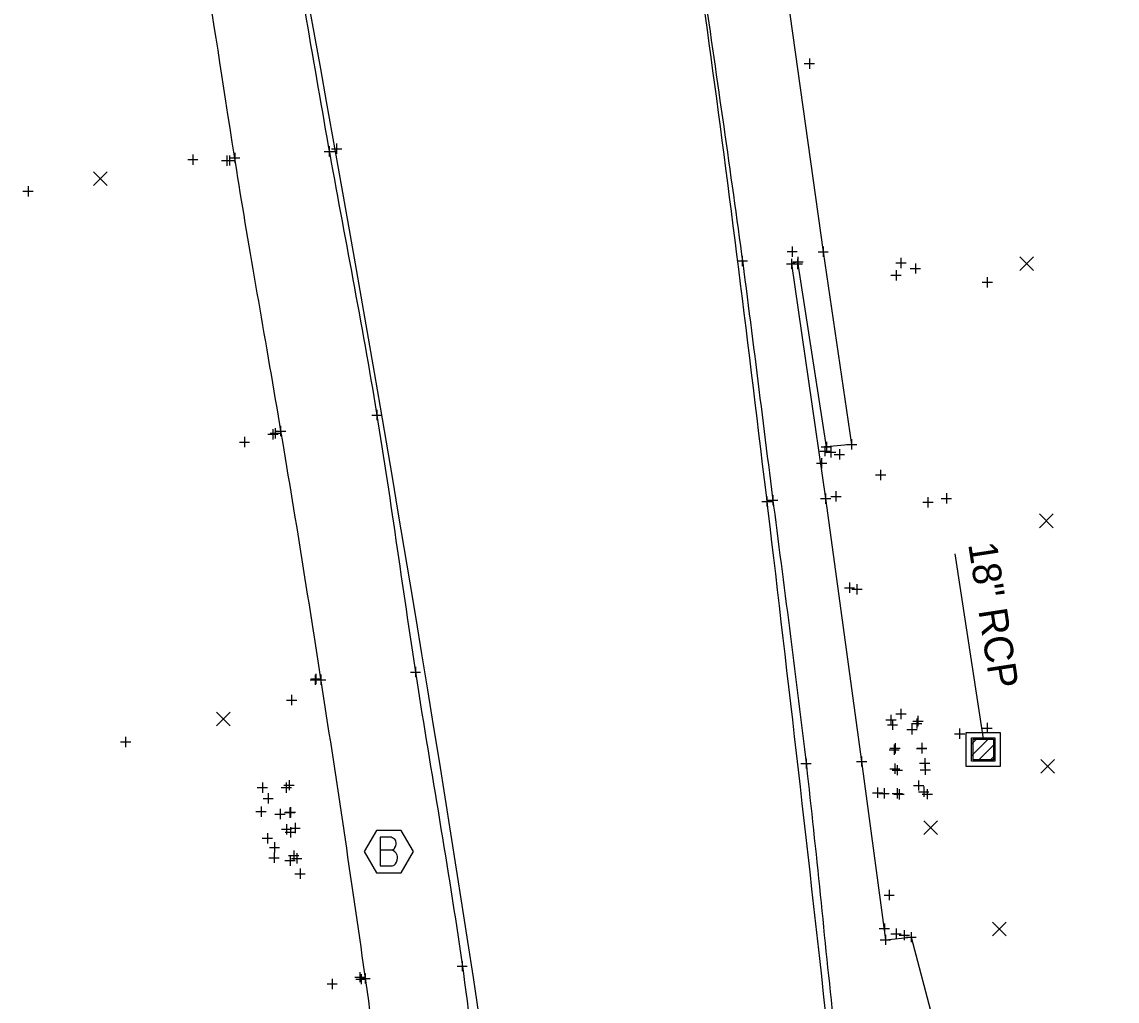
# Model space of a CAD drawing. Extents: x 2188719 to 2189819, y 654569 to 659504.
# Drawn here: x 2189678.2 to 2189785.2, y 658157.5 to 658253.3 of the extents above; entities that cross this region are included whole.
import ezdxf

# ---------------------------------------------------------------- set-up
doc = ezdxf.new("R2010")
doc.units = 0
for name, color, linetype in [('DR_X_Cells', 7, 'Continuous'), ('DR_X_Storm_Sewer', 7, 'Continuous'), ('DR_X_Text', 7, 'Continuous'), ('GK_Drainage_Nodes', 7, 'Continuous'), ('PM_X_Edge_Line', 7, 'Continuous'), ('PM_X_Transverse_Line', 7, 'Continuous'), ('PV_X_EOP', 7, 'Continuous'), ('PV_X_Shoulder', 7, 'Continuous'), ('RD_X_Cells', 7, 'Continuous'), ('SV_X_Random_Point', 7, 'Continuous'), ('SV_X_Shot_Marker', 7, 'Continuous')]:
    doc.layers.add(name, color=color, linetype=linetype)

msp = doc.modelspace()

# ---------------------------------------------------------------- linework, layer by layer
at = {"layer": 'DR_X_Cells'}
for p, q in [((2189770.99, 658181.51), (2189772.75, 658183.27)), ((2189770.99, 658182.65), (2189771.62, 658183.27)), ((2189771.59, 658180.98), (2189773.28, 658182.68)), ((2189772.72, 658180.98), (2189773.28, 658181.54))]:
    msp.add_line(p, q, dxfattribs=at)
for points in [[(2189770.47, 658183.79), (2189773.8, 658183.79), (2189773.8, 658180.46), (2189770.47, 658180.46)], [(2189770.99, 658183.27), (2189773.28, 658183.27), (2189773.28, 658180.98), (2189770.99, 658180.98)], [(2189771.14, 658183.13), (2189773.14, 658183.13), (2189773.14, 658181.13), (2189771.14, 658181.13)]]:
    msp.add_lwpolyline(points, close=True, dxfattribs=at)
at = {"layer": 'DR_X_Storm_Sewer'}
msp.add_line((2189772.17, 658183.17), (2189769.39, 658201.25), dxfattribs=at)
at = {"layer": 'GK_Drainage_Nodes'}
for p, q in [((2189772.14, 658183.79), (2189772.14, 658183.79)), ((2189772.14, 658183.13), (2189772.14, 658183.13)), ((2189771.14, 658182.13), (2189771.14, 658182.13)), ((2189772.14, 658182.13), (2189772.14, 658182.13)), ((2189772.14, 658182.13), (2189772.14, 658182.13)), ((2189772.14, 658182.13), (2189772.14, 658182.13)), ((2189773.14, 658182.13), (2189773.14, 658182.13)), ((2189772.14, 658181.13), (2189772.14, 658181.13)), ((2189772.14, 658180.46), (2189772.14, 658180.46))]:
    msp.add_line(p, q, dxfattribs=at)
at = {"layer": 'PM_X_Edge_Line'}
msp.add_open_spline([(2189715.92, 658416.15), (2189719.55, 658398.42), (2189727.31, 658355.37), (2189741.15, 658285.79), (2189752.08, 658199.49), (2189764.73, 658083.92), (2189776.67, 657949.48), (2189785.57, 657773.05), (2189784.87, 657651.45), (2189781.91, 657575.63)], degree=3, dxfattribs=at)
at = {"layer": 'PM_X_Transverse_Line'}
msp.add_open_spline([(2189687.91, 658347.82), (2189695.6, 658312.27), (2189724.53, 658165.17), (2189751.08, 657933.72), (2189754.2, 657738.17), (2189752.07, 657655.83)], degree=3, dxfattribs=at)
at = {"layer": 'PV_X_EOP'}
for points in [[(2189715.65, 658416.09), (2189717.36, 658407.13), (2189721.67, 658389.5), (2189726.25, 658363.76), (2189732.27, 658338.61), (2189735.95, 658313.21), (2189740.83, 658286.81), (2189744.4, 658258.95), (2189748.43, 658232.12), (2189751.61, 658205.72), (2189755.02, 658180.62), (2189757.39, 658155.27), (2189760.52, 658129.99), (2189762.73, 658103.87), (2189765.52, 658076.79), (2189767.84, 658049.53), (2189770.28, 658023.15), (2189773.03, 657997.24), (2189774.6, 657969.67), (2189777.01, 657941.26), (2189778.8, 657911.99), (2189780.69, 657884.09), (2189781.4, 657856.58), (2189782.11, 657829.65), (2189783.53, 657801.33), (2189783.56, 657772.66), (2189783.96, 657743.23), (2189783.95, 657715.3), (2189783.44, 657687.6), (2189783.88, 657660.21), (2189783.01, 657632.25), (2189782.93, 657604.05), (2189782.64, 657585.12), (2189782.5, 657575.65)], [(2189686.87, 658347.88), (2189688.95, 658339.56), (2189693.17, 658321.78), (2189697.87, 658294.9), (2189703.7, 658267.62), (2189707.98, 658241.03), (2189713.11, 658215.13), (2189716.61, 658188.45), (2189721.68, 658160.42), (2189724.61, 658131.33), (2189729.42, 658103.12), (2189732.17, 658074.94), (2189735.91, 658046.42), (2189738.42, 658016.97), (2189741.68, 657987.88), (2189743.15, 657958.86), (2189745.92, 657930.4), (2189747.37, 657902.49), (2189749.54, 657874.27), (2189750.21, 657845.72), (2189752.04, 657816.78), (2189752.93, 657788.08), (2189753.38, 657759.61), (2189754.01, 657732.65), (2189754.13, 657706.9), (2189754.02, 657681.8), (2189752.87, 657664.76), (2189752.08, 657656.03)]]:
    msp.add_open_spline(points, degree=3, dxfattribs=at)
at = {"layer": 'PV_X_Shoulder'}
for p, q in [((2189752.4, 658260.05), (2189756.49, 658230.8)), ((2189754.03, 658229.81), (2189753.4, 658229.61)), ((2189756.81, 658211.72), (2189754.03, 658229.81)), ((2189756.49, 658230.8), (2189759.27, 658211.96)), ((2189753.4, 658229.61), (2189756.73, 658206.66)), ((2189759.27, 658211.96), (2189756.81, 658211.72)), ((2189756.73, 658206.66), (2189760.25, 658180.96)), ((2189760.25, 658180.96), (2189762.57, 658163.53)), ((2189762.57, 658163.53), (2189765.08, 658163.79)), ((2189765.08, 658163.79), (2189767.29, 658155.51))]:
    msp.add_line(p, q, dxfattribs=at)
msp.add_open_spline([(2189678.17, 658346.51), (2189680.12, 658338.02), (2189683.83, 658320.14), (2189688.68, 658299.1), (2189690.22, 658284.76), (2189692.33, 658279.09), (2189693.11, 658275.51), (2189692.87, 658271.06), (2189696.13, 658259.46), (2189698.82, 658239.7), (2189703.41, 658214.08), (2189707.68, 658187.35), (2189711.85, 658159.43), (2189715.66, 658130.84), (2189719.89, 658102.92), (2189722.84, 658074.64), (2189726.21, 658045.96), (2189729.3, 658016.08), (2189731.79, 657986.57), (2189734.56, 657957.49), (2189736.24, 657929.57), (2189738.31, 657902.49), (2189739.34, 657874.4), (2189741.63, 657845.81), (2189742.72, 657816.8), (2189743.78, 657788), (2189744.99, 657759.47), (2189745.29, 657733.99), (2189744.96, 657716.97), (2189745.15, 657707.52), (2189744.91, 657697.88), (2189745.01, 657680.84), (2189744.6, 657665.71), (2189744.35, 657657.17)], degree=3, dxfattribs=at)
at = {"layer": 'RD_X_Cells'}
for p, q in [((2189712.84, 658174.23), (2189711.64, 658172.16)), ((2189715.24, 658174.23), (2189712.84, 658174.23)), ((2189716.44, 658172.16), (2189715.24, 658174.23)), ((2189711.64, 658172.16), (2189712.84, 658170.08)), ((2189715.24, 658170.08), (2189716.44, 658172.16)), ((2189712.84, 658170.08), (2189715.24, 658170.08))]:
    msp.add_line(p, q, dxfattribs=at)
msp.add_lwpolyline([(2189714.4, 658172.28), (2189714.51, 658172.39), (2189714.58, 658172.45), (2189714.62, 658172.52), (2189714.64, 658172.56), (2189714.69, 658172.65), (2189714.71, 658172.72), (2189714.75, 658172.87), (2189714.75, 658172.94), (2189714.75, 658173.03), (2189714.73, 658173.16), (2189714.69, 658173.27), (2189714.62, 658173.36), (2189714.51, 658173.45), (2189714.42, 658173.49), (2189714.38, 658173.51), (2189714.27, 658173.56), (2189713.19, 658173.56), (2189713.19, 658170.76), (2189714.4, 658170.76), (2189714.56, 658170.84), (2189714.69, 658170.95), (2189714.8, 658171.13), (2189714.86, 658171.33), (2189714.89, 658171.53), (2189714.89, 658171.66), (2189714.84, 658171.79), (2189714.75, 658171.99), (2189714.64, 658172.12), (2189714.4, 658172.28), (2189713.19, 658172.28)], dxfattribs=at)
at = {"layer": 'SV_X_Random_Point'}
for p, q in [((2189685.18, 658237.26), (2189686.51, 658238.59)), ((2189685.18, 658238.59), (2189686.51, 658237.26)), ((2189775.72, 658228.96), (2189777.05, 658230.3)), ((2189775.72, 658230.3), (2189777.05, 658228.96)), ((2189777.62, 658203.82), (2189778.96, 658205.16)), ((2189777.62, 658205.16), (2189778.96, 658203.82)), ((2189697.19, 658184.46), (2189698.53, 658185.79)), ((2189697.19, 658185.79), (2189698.53, 658184.46)), ((2189777.76, 658179.82), (2189779.09, 658181.16)), ((2189777.76, 658181.16), (2189779.09, 658179.82)), ((2189766.33, 658173.83), (2189767.66, 658175.17)), ((2189766.33, 658175.17), (2189767.66, 658173.83)), ((2189773.04, 658163.91), (2189774.38, 658165.24)), ((2189773.04, 658165.24), (2189774.38, 658163.91))]:
    msp.add_line(p, q, dxfattribs=at)
at = {"layer": 'SV_X_Shot_Marker'}
for p, q in [((2189754.65, 658249.19), (2189755.65, 658249.19)), ((2189755.15, 658249.69), (2189755.15, 658248.69)), ((2189755.15, 658249.19), (2189755.15, 658249.19)), ((2189707.72, 658240.6), (2189708.72, 658240.6)), ((2189708.22, 658241.1), (2189708.22, 658240.1)), ((2189708.22, 658240.6), (2189708.22, 658240.6)), ((2189708.43, 658240.86), (2189709.43, 658240.86)), ((2189708.93, 658241.36), (2189708.93, 658240.36)), ((2189708.93, 658240.86), (2189708.93, 658240.86)), ((2189694.38, 658239.8), (2189695.38, 658239.8)), ((2189694.88, 658240.3), (2189694.88, 658239.3)), ((2189694.88, 658239.8), (2189694.88, 658239.8)), ((2189697.69, 658239.7), (2189698.69, 658239.7)), ((2189697.95, 658239.71), (2189698.95, 658239.71)), ((2189698.19, 658240.2), (2189698.19, 658239.2)), ((2189698.19, 658239.7), (2189698.19, 658239.7)), ((2189698.45, 658240.21), (2189698.45, 658239.21)), ((2189698.45, 658239.71), (2189698.45, 658239.71)), ((2189698.47, 658239.96), (2189699.47, 658239.96)), ((2189698.97, 658240.46), (2189698.97, 658239.46)), ((2189698.97, 658239.96), (2189698.97, 658239.96)), ((2189678.28, 658236.7), (2189679.28, 658236.7)), ((2189678.78, 658237.2), (2189678.78, 658236.2)), ((2189678.78, 658236.7), (2189678.78, 658236.7)), ((2189753.46, 658231.31), (2189753.46, 658230.31)), ((2189756.49, 658231.3), (2189756.49, 658230.3)), ((2189748.09, 658229.9), (2189749.09, 658229.9)), ((2189748.59, 658230.4), (2189748.59, 658229.4)), ((2189748.59, 658229.9), (2189748.59, 658229.9)), ((2189752.96, 658230.81), (2189753.96, 658230.81)), ((2189753.4, 658230.11), (2189753.4, 658229.11)), ((2189753.46, 658230.81), (2189753.46, 658230.81)), ((2189753.53, 658229.81), (2189754.53, 658229.81)), ((2189753.97, 658230.1), (2189753.97, 658229.1)), ((2189754.03, 658230.31), (2189754.03, 658229.31)), ((2189754.03, 658229.81), (2189754.03, 658229.81)), ((2189755.99, 658230.8), (2189756.99, 658230.8)), ((2189756.49, 658230.8), (2189756.49, 658230.8)), ((2189764.09, 658230.2), (2189764.09, 658229.2)), ((2189752.9, 658229.61), (2189753.9, 658229.61)), ((2189753.4, 658229.61), (2189753.4, 658229.61)), ((2189753.47, 658229.6), (2189754.47, 658229.6)), ((2189753.97, 658229.6), (2189753.97, 658229.6)), ((2189763.59, 658229.7), (2189764.59, 658229.7)), ((2189763.61, 658228.99), (2189763.61, 658227.99)), ((2189764.09, 658229.7), (2189764.09, 658229.7)), ((2189765, 658229.16), (2189766, 658229.16)), ((2189765.5, 658229.66), (2189765.5, 658228.66)), ((2189765.5, 658229.16), (2189765.5, 658229.16)), ((2189763.11, 658228.49), (2189764.11, 658228.49)), ((2189763.61, 658228.49), (2189763.61, 658228.49)), ((2189772.03, 658227.81), (2189773.03, 658227.81)), ((2189772.53, 658228.31), (2189772.53, 658227.31)), ((2189772.53, 658227.81), (2189772.53, 658227.81)), ((2189712.37, 658214.83), (2189713.37, 658214.83)), ((2189712.87, 658215.33), (2189712.87, 658214.33)), ((2189712.87, 658214.83), (2189712.87, 658214.83)), ((2189703.46, 658213.76), (2189703.46, 658212.76)), ((2189699.93, 658212.69), (2189699.93, 658211.69)), ((2189702.21, 658212.95), (2189703.21, 658212.95)), ((2189702.44, 658213.05), (2189703.44, 658213.05)), ((2189702.71, 658213.45), (2189702.71, 658212.45)), ((2189702.71, 658212.95), (2189702.71, 658212.95)), ((2189702.94, 658213.55), (2189702.94, 658212.55)), ((2189702.94, 658213.05), (2189702.94, 658213.05)), ((2189702.96, 658213.26), (2189703.96, 658213.26)), ((2189703.46, 658213.26), (2189703.46, 658213.26)), ((2189699.43, 658212.19), (2189700.43, 658212.19)), ((2189699.93, 658212.19), (2189699.93, 658212.19)), ((2189756.31, 658211.72), (2189757.31, 658211.72)), ((2189756.67, 658211.8), (2189756.67, 658210.8)), ((2189756.81, 658212.22), (2189756.81, 658211.22)), ((2189756.81, 658211.72), (2189756.81, 658211.72)), ((2189757.23, 658211.69), (2189757.23, 658210.69)), ((2189758.77, 658211.96), (2189759.77, 658211.96)), ((2189759.27, 658212.46), (2189759.27, 658211.46)), ((2189759.27, 658211.96), (2189759.27, 658211.96)), ((2189756.17, 658211.3), (2189757.17, 658211.3)), ((2189756.34, 658210.61), (2189756.34, 658209.61)), ((2189756.67, 658211.3), (2189756.67, 658211.3)), ((2189756.73, 658211.19), (2189757.73, 658211.19)), ((2189757.23, 658211.19), (2189757.23, 658211.19)), ((2189757.58, 658210.98), (2189758.58, 658210.98)), ((2189758.08, 658211.48), (2189758.08, 658210.48)), ((2189758.08, 658210.98), (2189758.08, 658210.98)), ((2189755.84, 658210.11), (2189756.84, 658210.11)), ((2189756.34, 658210.11), (2189756.34, 658210.11)), ((2189762.11, 658209.48), (2189762.11, 658208.48)), ((2189761.61, 658208.98), (2189762.61, 658208.98)), ((2189762.11, 658208.98), (2189762.11, 658208.98)), ((2189757.74, 658207.38), (2189757.74, 658206.38)), ((2189750.5, 658206.38), (2189751.5, 658206.38)), ((2189751, 658206.88), (2189751, 658205.88)), ((2189751, 658206.38), (2189751, 658206.38)), ((2189751.07, 658206.51), (2189752.07, 658206.51)), ((2189751.57, 658207.01), (2189751.57, 658206.01)), ((2189751.57, 658206.51), (2189751.57, 658206.51)), ((2189756.23, 658206.66), (2189757.23, 658206.66)), ((2189756.73, 658207.16), (2189756.73, 658206.16)), ((2189756.73, 658206.66), (2189756.73, 658206.66)), ((2189757.24, 658206.88), (2189758.24, 658206.88)), ((2189757.74, 658206.88), (2189757.74, 658206.88)), ((2189766.23, 658206.3), (2189767.23, 658206.3)), ((2189766.73, 658206.8), (2189766.73, 658205.8)), ((2189766.73, 658206.3), (2189766.73, 658206.3)), ((2189768.04, 658206.68), (2189769.04, 658206.68)), ((2189768.54, 658207.18), (2189768.54, 658206.18)), ((2189768.54, 658206.68), (2189768.54, 658206.68)), ((2189758.56, 658197.95), (2189759.56, 658197.95)), ((2189759.06, 658198.45), (2189759.06, 658197.45)), ((2189759.06, 658197.95), (2189759.06, 658197.95)), ((2189759.29, 658197.8), (2189760.29, 658197.8)), ((2189759.79, 658198.3), (2189759.79, 658197.3)), ((2189759.79, 658197.8), (2189759.79, 658197.8)), ((2189716.64, 658190.2), (2189716.64, 658189.2)), ((2189706.85, 658189.45), (2189706.85, 658188.45)), ((2189706.9, 658189.53), (2189706.9, 658188.53)), ((2189707.38, 658189.46), (2189707.38, 658188.46)), ((2189716.14, 658189.7), (2189717.14, 658189.7)), ((2189716.64, 658189.7), (2189716.64, 658189.7)), ((2189706.35, 658188.95), (2189707.35, 658188.95)), ((2189706.4, 658189.03), (2189707.4, 658189.03)), ((2189706.85, 658188.95), (2189706.85, 658188.95)), ((2189706.88, 658188.96), (2189707.88, 658188.96)), ((2189706.9, 658189.03), (2189706.9, 658189.03)), ((2189707.38, 658188.96), (2189707.38, 658188.96)), ((2189704.54, 658187.47), (2189704.54, 658186.47)), ((2189704.04, 658186.97), (2189705.04, 658186.97)), ((2189704.54, 658186.97), (2189704.54, 658186.97)), ((2189764.09, 658186.11), (2189764.09, 658185.11)), ((2189762.61, 658185.03), (2189763.61, 658185.03)), ((2189763.11, 658185.53), (2189763.11, 658184.53)), ((2189763.11, 658185.03), (2189763.11, 658185.03)), ((2189763.27, 658185.06), (2189763.27, 658184.06)), ((2189763.59, 658185.61), (2189764.59, 658185.61)), ((2189764.09, 658185.61), (2189764.09, 658185.61)), ((2189765.25, 658184.91), (2189766.25, 658184.91)), ((2189765.63, 658185.18), (2189765.63, 658184.18)), ((2189765.75, 658185.41), (2189765.75, 658184.41)), ((2189765.75, 658184.91), (2189765.75, 658184.91)), ((2189762.77, 658184.56), (2189763.77, 658184.56)), ((2189763.27, 658184.56), (2189763.27, 658184.56)), ((2189764.67, 658184.09), (2189765.67, 658184.09)), ((2189765.13, 658184.68), (2189766.13, 658184.68)), ((2189765.17, 658184.59), (2189765.17, 658183.59)), ((2189765.17, 658184.09), (2189765.17, 658184.09)), ((2189765.63, 658184.68), (2189765.63, 658184.68)), ((2189769.83, 658184.18), (2189769.83, 658183.18)), ((2189772.02, 658184.23), (2189773.02, 658184.23)), ((2189772.52, 658184.73), (2189772.52, 658183.73)), ((2189772.52, 658184.23), (2189772.52, 658184.23)), ((2189687.81, 658182.87), (2189688.81, 658182.87)), ((2189688.31, 658183.37), (2189688.31, 658182.37)), ((2189688.31, 658182.87), (2189688.31, 658182.87)), ((2189763.52, 658182.75), (2189763.52, 658181.75)), ((2189766.12, 658182.74), (2189766.12, 658181.74)), ((2189766.13, 658182.77), (2189766.13, 658181.77)), ((2189769.33, 658183.68), (2189770.33, 658183.68)), ((2189769.83, 658183.68), (2189769.83, 658183.68)), ((2189762.93, 658182.11), (2189763.93, 658182.11)), ((2189763.02, 658182.25), (2189764.02, 658182.25)), ((2189763.43, 658182.61), (2189763.43, 658181.61)), ((2189763.43, 658182.11), (2189763.43, 658182.11)), ((2189763.52, 658182.25), (2189763.52, 658182.25)), ((2189765.62, 658182.24), (2189766.62, 658182.24)), ((2189765.63, 658182.27), (2189766.63, 658182.27)), ((2189766.12, 658182.24), (2189766.12, 658182.24)), ((2189766.13, 658182.27), (2189766.13, 658182.27)), ((2189754.32, 658180.77), (2189755.32, 658180.77)), ((2189754.82, 658181.27), (2189754.82, 658180.27)), ((2189754.82, 658180.77), (2189754.82, 658180.77)), ((2189759.75, 658180.96), (2189760.75, 658180.96)), ((2189760.25, 658181.46), (2189760.25, 658180.46)), ((2189760.25, 658180.96), (2189760.25, 658180.96)), ((2189763.5, 658180.76), (2189763.5, 658179.76)), ((2189763.74, 658180.61), (2189763.74, 658179.61)), ((2189765.92, 658180.8), (2189766.92, 658180.8)), ((2189766.42, 658181.3), (2189766.42, 658180.3)), ((2189766.42, 658180.8), (2189766.42, 658180.8)), ((2189766.47, 658180.66), (2189766.47, 658179.66)), ((2189763, 658180.26), (2189764, 658180.26)), ((2189763.24, 658180.11), (2189764.24, 658180.11)), ((2189763.5, 658180.26), (2189763.5, 658180.26)), ((2189763.74, 658180.11), (2189763.74, 658180.11)), ((2189765.97, 658180.16), (2189766.97, 658180.16)), ((2189766.47, 658180.16), (2189766.47, 658180.16)), ((2189701.68, 658178.91), (2189701.68, 658177.91)), ((2189703.79, 658178.65), (2189704.79, 658178.65)), ((2189704.01, 658178.91), (2189704.01, 658177.91)), ((2189704.29, 658179.15), (2189704.29, 658178.15)), ((2189704.29, 658178.65), (2189704.29, 658178.65)), ((2189765.32, 658178.62), (2189766.32, 658178.62)), ((2189765.82, 658179.12), (2189765.82, 658178.12)), ((2189765.82, 658178.62), (2189765.82, 658178.62)), ((2189766.32, 658178.51), (2189766.32, 658177.51)), ((2189701.18, 658178.41), (2189702.18, 658178.41)), ((2189701.68, 658178.41), (2189701.68, 658178.41)), ((2189702.24, 658177.85), (2189702.24, 658176.85)), ((2189703.51, 658178.41), (2189704.51, 658178.41)), ((2189704.01, 658178.41), (2189704.01, 658178.41)), ((2189761.31, 658177.91), (2189762.31, 658177.91)), ((2189761.81, 658178.41), (2189761.81, 658177.41)), ((2189761.81, 658177.91), (2189761.81, 658177.91)), ((2189761.95, 658177.84), (2189762.95, 658177.84)), ((2189762.45, 658178.34), (2189762.45, 658177.34)), ((2189762.45, 658177.84), (2189762.45, 658177.84)), ((2189763.24, 658177.84), (2189764.24, 658177.84)), ((2189763.41, 658177.76), (2189764.41, 658177.76)), ((2189763.74, 658178.34), (2189763.74, 658177.34)), ((2189763.74, 658177.84), (2189763.74, 658177.84)), ((2189763.91, 658178.26), (2189763.91, 658177.26)), ((2189763.91, 658177.76), (2189763.91, 658177.76)), ((2189765.82, 658178.01), (2189766.82, 658178.01)), ((2189766.17, 658177.77), (2189767.17, 658177.77)), ((2189766.32, 658178.01), (2189766.32, 658178.01)), ((2189766.67, 658178.27), (2189766.67, 658177.27)), ((2189766.67, 658177.77), (2189766.67, 658177.77)), ((2189701.55, 658176.56), (2189701.55, 658175.56)), ((2189701.74, 658177.35), (2189702.74, 658177.35)), ((2189702.24, 658177.35), (2189702.24, 658177.35)), ((2189703.41, 658176.32), (2189703.41, 658175.32)), ((2189704.35, 658176.47), (2189704.35, 658175.47)), ((2189704.42, 658176.5), (2189704.42, 658175.5)), ((2189701.05, 658176.06), (2189702.05, 658176.06)), ((2189701.55, 658176.06), (2189701.55, 658176.06)), ((2189702.91, 658175.82), (2189703.91, 658175.82)), ((2189703.41, 658175.82), (2189703.41, 658175.82)), ((2189703.85, 658175.97), (2189704.85, 658175.97)), ((2189703.92, 658176), (2189704.92, 658176)), ((2189704.35, 658175.97), (2189704.35, 658175.97)), ((2189704.42, 658176), (2189704.42, 658176)), ((2189703.54, 658174.34), (2189704.54, 658174.34)), ((2189704.04, 658174.84), (2189704.04, 658173.84)), ((2189704.04, 658174.34), (2189704.04, 658174.34)), ((2189704.38, 658174.46), (2189705.38, 658174.46)), ((2189704.42, 658174.54), (2189704.42, 658173.54)), ((2189704.88, 658174.96), (2189704.88, 658173.96)), ((2189704.88, 658174.46), (2189704.88, 658174.46)), ((2189701.67, 658173.46), (2189702.67, 658173.46)), ((2189702.17, 658173.96), (2189702.17, 658172.96)), ((2189702.17, 658173.46), (2189702.17, 658173.46)), ((2189703.92, 658174.04), (2189704.92, 658174.04)), ((2189704.42, 658174.04), (2189704.42, 658174.04)), ((2189702.36, 658172.56), (2189703.36, 658172.56)), ((2189702.82, 658172.06), (2189702.82, 658171.06)), ((2189702.86, 658173.06), (2189702.86, 658172.06)), ((2189702.86, 658172.56), (2189702.86, 658172.56)), ((2189704.74, 658172.26), (2189704.74, 658171.26)), ((2189702.32, 658171.56), (2189703.32, 658171.56)), ((2189702.82, 658171.56), (2189702.82, 658171.56)), ((2189703.88, 658171.27), (2189704.88, 658171.27)), ((2189704.24, 658171.76), (2189705.24, 658171.76)), ((2189704.38, 658171.77), (2189704.38, 658170.77)), ((2189704.38, 658171.27), (2189704.38, 658171.27)), ((2189704.54, 658171.49), (2189705.54, 658171.49)), ((2189704.74, 658171.76), (2189704.74, 658171.76)), ((2189705.04, 658171.99), (2189705.04, 658170.99)), ((2189705.04, 658171.49), (2189705.04, 658171.49)), ((2189704.86, 658169.99), (2189705.86, 658169.99)), ((2189705.36, 658170.49), (2189705.36, 658169.49)), ((2189705.36, 658169.99), (2189705.36, 658169.99)), ((2189762.44, 658167.9), (2189763.44, 658167.9)), ((2189762.94, 658168.4), (2189762.94, 658167.4)), ((2189762.94, 658167.9), (2189762.94, 658167.9)), ((2189761.98, 658164.64), (2189762.98, 658164.64)), ((2189762.48, 658165.14), (2189762.48, 658164.14)), ((2189762.48, 658164.64), (2189762.48, 658164.64)), ((2189763.61, 658164.62), (2189763.61, 658163.62)), ((2189762.07, 658163.53), (2189763.07, 658163.53)), ((2189762.57, 658164.03), (2189762.57, 658163.03)), ((2189762.57, 658163.53), (2189762.57, 658163.53)), ((2189763.11, 658164.12), (2189764.11, 658164.12)), ((2189763.61, 658164.12), (2189763.61, 658164.12)), ((2189763.92, 658163.98), (2189764.92, 658163.98)), ((2189764.42, 658164.48), (2189764.42, 658163.48)), ((2189764.42, 658163.98), (2189764.42, 658163.98)), ((2189764.58, 658163.79), (2189765.58, 658163.79)), ((2189765.08, 658164.29), (2189765.08, 658163.29)), ((2189765.08, 658163.79), (2189765.08, 658163.79)), ((2189721.21, 658161.45), (2189721.21, 658160.45)), ((2189711.21, 658160.38), (2189711.21, 658159.38)), ((2189711.72, 658160.25), (2189711.72, 658159.25)), ((2189720.71, 658160.95), (2189721.71, 658160.95)), ((2189721.21, 658160.95), (2189721.21, 658160.95)), ((2189708, 658159.22), (2189709, 658159.22)), ((2189708.5, 658159.72), (2189708.5, 658158.72)), ((2189708.5, 658159.22), (2189708.5, 658159.22)), ((2189710.71, 658159.88), (2189711.71, 658159.88)), ((2189710.82, 658159.68), (2189711.82, 658159.68)), ((2189711.21, 658159.88), (2189711.21, 658159.88)), ((2189711.22, 658159.75), (2189712.22, 658159.75)), ((2189711.32, 658160.18), (2189711.32, 658159.18)), ((2189711.32, 658159.68), (2189711.32, 658159.68)), ((2189711.72, 658159.75), (2189711.72, 658159.75))]:
    msp.add_line(p, q, dxfattribs=at)

# ---------------------------------------------------------------- texts
at = {"layer": 'DR_X_Text'}
msp.add_text('18" RCP', height=2.8, rotation=278.7282, dxfattribs=at).set_placement((2189770.66, 658202.21))

doc.saveas('drawing.dxf')
